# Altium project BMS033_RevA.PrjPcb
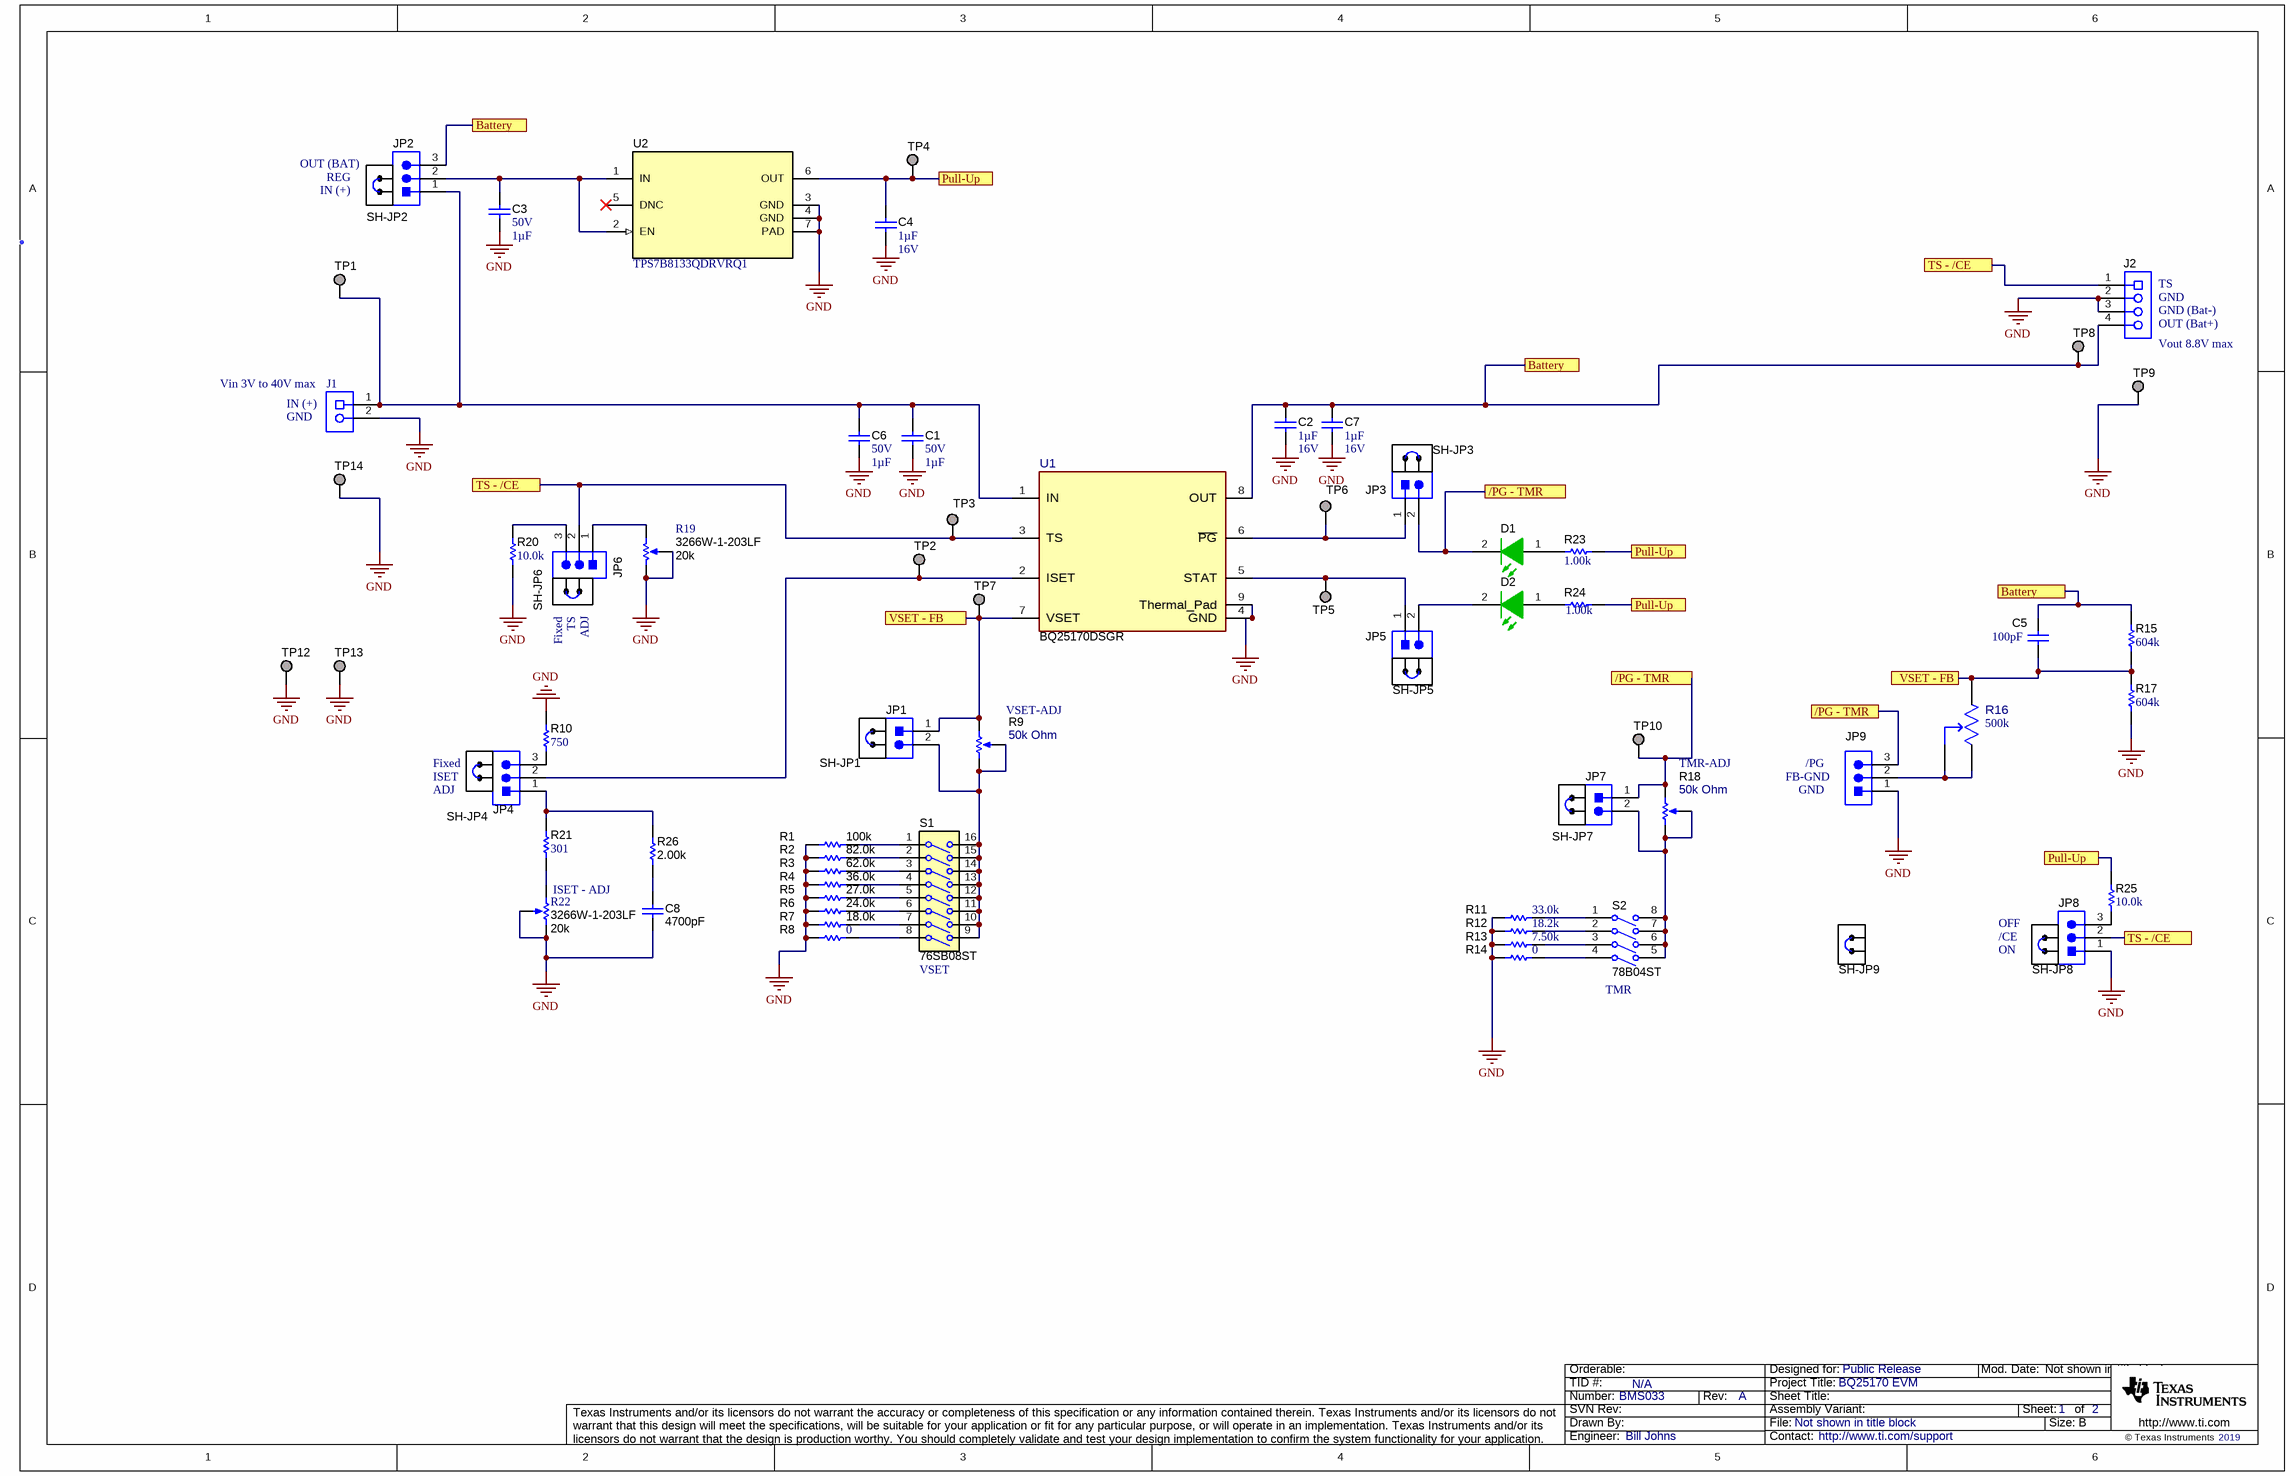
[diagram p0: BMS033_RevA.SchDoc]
CopyrightYear: 2019; PCB_Layout: Krypton Solutions / JMM; PCB_Rev: A; PRJ_Customer: Public Release; PRJ_Engineer: Bill Johns; PRJ_Number: BMS033; PRJ_Title: BQ25170 EVM; SCH_Rev: A; TechSupport: http://www.ti.com/support; TID: N/A
2 sheets, 86 parts. Net scope: flat (ports and power ports of the same name join across sheets).
Board file: BMS033_RevA.PcbDoc
Sheets:
  BMS033_RevA.SchDoc
  BMS033_RevA_Hardware.SchDoc

## Sheet BMS033_RevA.SchDoc
size 431 x 279 mm; Date: Not shown in title block; ApprovedBy: Not shown in title block; CheckedBy: Not shown in title block; Author: Not shown in title block; CompanyName: Not shown in title block; Engineer: Not shown in title block; Organization: Not shown in title block; Address1: Not shown in title block; Address2: Not shown in title block; Address3: Not shown in title block; Address4: Not shown in title block; DocumentNumber: 1; Revision: Use project parameter SCH_Rev; SheetNumber: 1; SheetTotal: 2; PageSetup: Record=PageOptions¦CenterHorizontal=True¦CenterVertical=True¦PrintScale=1.00¦XCorrection=1.00¦YCorrection=1.00¦PrintKind=0¦BorderSize=5000000¦LeftOffset=0¦BottomOffset=0¦Orientation=2¦PaperLength=1000¦PaperWidth=1000¦Scale=100¦PaperSource=15¦PrintQuality=600¦MediaType=1¦DitherType=10¦PaperKind=Letter¦PrintScaleMode=1

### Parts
C1  VDC_V: 50V  ValueDisplayed: 1µF  [0603]  (hidden comment: GRT188R61H105ME13D)
C2  Cap_F: 1µF  VDC_V: 16V  [0603]  (hidden comment: GCM188R71C105KA64D)
C3  VDC_V: 50V  ValueDisplayed: 1µF  [0603]  (hidden comment: GRT188R61H105ME13D)
C4  Cap_F: 1µF  VDC_V: 16V  [0603]  (hidden comment: GCM188R71C105KA64D)
C5  value 100pF  [0402]  (hidden comment: 04025A101FAT2A)
C6  VDC_V: 50V  ValueDisplayed: 1µF  [0603]  (hidden comment: GRT188R61H105ME13D)
C7  Cap_F: 1µF  VDC_V: 16V  [0603]  (hidden comment: GCM188R71C105KA64D)
C8  ValueDisplayed: 4700pF  [0603]  (hidden comment: C0603C104K9PAC7867)
D1  LTST-C193TGKT-5A  [LTST-C193_Green_S]  (value not drawn)
D2  LTST-C193TGKT-5A  [LTST-C193_Green_S]  (value not drawn)
J1  ED555/2DS  [TERM_BLK_ED555-2DS]  (value not drawn)
J2  ED555/4DS  [TERM_BLK_ED555-4DS]  (value not drawn)
JP1  PEC02SAAN  [CONN_PEC02SAAN]  (value not drawn)
JP2  PEC03SAAN  [CONN_PEC03SAAN]  (value not drawn)
JP3  PEC02SAAN  [CONN_PEC02SAAN]  (value not drawn)
JP4  PEC03SAAN  [CONN_PEC03SAAN]  (value not drawn)
JP5  PEC02SAAN  [CONN_PEC02SAAN]  (value not drawn)
JP6  PEC03SAAN  [CONN_PEC03SAAN]  (value not drawn)
JP7  PEC02SAAN  [CONN_PEC02SAAN]  (value not drawn)
JP8  PEC03SAAN  [CONN_PEC03SAAN]  (value not drawn)
JP9  PEC03SAAN  [CONN_PEC03SAAN]  (value not drawn)
R1  ValueDisplayed: 100k  [0603]  (hidden comment: RC0603FR-0775KL)
R2  ValueDisplayed: 82.0k  [0603]  (hidden comment: RC0603FR-0733KL)
R3  ValueDisplayed: 62.0k  [0603]  (hidden comment: RC0603FR-0727K4L)
R4  ValueDisplayed: 36.0k  [0603]  (hidden comment: RC0603FR-0722K1L)
R5  ValueDisplayed: 27.0k  [0603]  (hidden comment: RC0603FR-077K5L)
R6  ValueDisplayed: 24.0k  [0603]  (hidden comment: RC0603FR-075K6L)
R7  ValueDisplayed: 18.0k  [0603]  (hidden comment: RC0603FR-073K32L)
R8  ValueDisplayed: 0  [0603]  (hidden comment: RC0603JR-070RL)
R9  value 50k Ohm  [Bourns_PV37W]  (hidden comment: PV37W503C01B00)
R10  ValueDisplayed: 750  [0603]  (hidden comment: RC0603FR-07750RL)
R11  ValueDisplayed: 33.0k  [0603]  (hidden comment: RC0603FR-0733KL)
R12  ValueDisplayed: 18.2k  [0603]  (hidden comment: RC0603FR-0718K2L)
R13  ValueDisplayed: 7.50k  [0603]  (hidden comment: RC0603FR-077K5L)
R14  ValueDisplayed: 0  [0603]  (hidden comment: RC0603JR-070RL)
R15  ValueDisplayed: 604k  [0805L]  (hidden comment: RT0805BRD07604KL)
R16  PV37W504C01B00  [FP-PV37W504C01B00_PTH_3-MFG]  (value not drawn)
R17  ValueDisplayed: 604k  [0805L]  (hidden comment: RT0805BRD07604KL)
R18  value 50k Ohm  [Bourns_PV37W]  (hidden comment: PV37W503C01B00)
R19  3266W-1-203LF  value 20k  [TRIM_3266W]
R20  ValueDisplayed: 10.0k  [0603]  (hidden comment: CRCW060310K0FKEA)
R21  ValueDisplayed: 301  [0603]  (hidden comment: CRCW0603301RFKEA)
R22  3266W-1-203LF  value 20k  [TRIM_3266W]
R23  ValueDisplayed: 1.00k  [0603]  (hidden comment: RC0603FR-071KL)
R24  ValueDisplayed: 1.00k  [0603]  (hidden comment: RC0603FR-071KL)
R25  ValueDisplayed: 10.0k  [0603]  (hidden comment: CRCW060310K0FKEA)
R26  ValueDisplayed: 2.00k  [0603]  (hidden comment: CRCW06032K00FKEA)
S1  76SB08ST  [SW_76SB08ST]
S2  78B04ST  [SW_78B04ST]
SH-JP1  SNT-100-BK-G  [SNT-100-BK-G]  (value not drawn)
SH-JP2  SNT-100-BK-G  [SNT-100-BK-G]  (value not drawn)
SH-JP3  SNT-100-BK-G  [SNT-100-BK-G]  (value not drawn)
SH-JP4  SNT-100-BK-G  [SNT-100-BK-G]  (value not drawn)
SH-JP5  SNT-100-BK-G  [SNT-100-BK-G]  (value not drawn)
SH-JP6  SNT-100-BK-G  [SNT-100-BK-G]  (value not drawn)
SH-JP7  SNT-100-BK-G  [SNT-100-BK-G]  (value not drawn)
SH-JP8  SNT-100-BK-G  [SNT-100-BK-G]  (value not drawn)
SH-JP9  SNT-100-BK-G  [SNT-100-BK-G]  (value not drawn)
TP1  S1751-46  [Harwin_S1751-46]  (value not drawn)
TP2  S1751-46  [Harwin_S1751-46]  (value not drawn)
TP3  S1751-46  [Harwin_S1751-46]  (value not drawn)
TP4  S1751-46  [Harwin_S1751-46]  (value not drawn)
TP5  S1751-46  [Harwin_S1751-46]  (value not drawn)
TP6  S1751-46  [Harwin_S1751-46]  (value not drawn)
TP7  S1751-46  [Harwin_S1751-46]  (value not drawn)
TP8  S1751-46  [Harwin_S1751-46]  (value not drawn)
TP9  S1751-46  [Harwin_S1751-46]  (value not drawn)
TP10  S1751-46  [Harwin_S1751-46]  (value not drawn)
TP12  S1751-46  [Harwin_S1751-46]  (value not drawn)
TP13  S1751-46  [Harwin_S1751-46]  (value not drawn)
TP14  S1751-46  [Harwin_S1751-46]  (value not drawn)
U1  PartNumber: BQ25170DSGR  [DSG0008A]  (hidden comment: BQ25170DSG)
U2  TPS7B8133QDRVRQ1  [DRV0006A]  (no BOM)

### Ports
/PG - TMR, Battery, Pull-Up, TS - /CE, VSET - FB

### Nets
GND: C1.2 C2.2 C3.2 C4.2 C6.2 C7.2 C8.1 J1.2 J2.2 J2.3 JP8.1 JP9.1 R1.1 R2.1 R3.1 R4.1 R5.1 R6.1 R7.1 R8.1 R10.2 R11.1 R12.1 R13.1 R14.1 R17.1 R19.2(WIPER) R19.3(CW) R20.1 R22.2(WIPER) R22.3(CW) TP9.1 TP12.1 TP13.1 TP14.1 U1.4(GND) U1.9(Thermal_Pad) U2.3(GND) U2.4(GND) U2.7(PAD)
/PG - TMR: D1.2(K) JP3.2 JP7.1 JP9.3 R18.3(CW) TP10.1 ; port /PG - TMR
Battery: C2.1 C5.1 C7.1 J2.4 JP2.3 R15.2 TP8.1 U1.8(OUT) ; port Battery
Pull-Up: C4.1 R23.2 R24.2 R25.2 TP4.1 U2.6(OUT) ; port Pull-Up
TS - /CE: J2.1 JP6.2 JP8.2 TP3.1 U1.3(TS) ; port TS - /CE
VSET - FB: C5.2 JP1.1 R9.3(CW) R15.1 R16.3 R17.2 TP7.1 U1.7(VSET) ; port VSET - FB
NetC1_1: C1.1 C6.1 J1.1 JP2.1 TP1.1 U1.1(IN)
NetC3_1: C3.1 JP2.2 U2.1(IN) U2.2(EN)
NetC8_2: C8.2 R26.2
NetD1_1: D1.1(A) R23.1
NetD2_1: D2.1(A) R24.1
NetD2_2: D2.2(K) JP5.2
NetJP1_2: JP1.2 R9.1(CCW) R9.2(WIPER) S1.9(8A) S1.10(7A) S1.11(6A) S1.12(5A) S1.13(4A) S1.14(3A) S1.15(2A) S1.16(1A)
NetJP3_1: JP3.1 TP6.1 U1.6(~{PG})
NetJP4_1: JP4.1 R21.2 R26.1
NetJP4_2: JP4.2 TP2.1 U1.2(ISET)
NetJP4_3: JP4.3 R10.1
NetJP5_1: JP5.1 TP5.1 U1.5(STAT)
NetJP6_1: JP6.1 R19.1(CCW)
NetJP6_3: JP6.3 R20.2
NetJP7_2: JP7.2 R18.1(CCW) R18.2(WIPER) S2.5(B4) S2.6(B3) S2.7(B2) S2.8(B1)
NetJP8_3: JP8.3 R25.1
NetJP9_2: JP9.2 R16.1 R16.2
NetR1_2: R1.2 S1.1
NetR2_2: R2.2 S1.2
NetR3_2: R3.2 S1.3
NetR4_2: R4.2 S1.4
NetR5_2: R5.2 S1.5
NetR6_2: R6.2 S1.6
NetR7_2: R7.2 S1.7
NetR8_2: R8.2 S1.8
NetR11_2: R11.2 S2.1(A1)
NetR12_2: R12.2 S2.2(A2)
NetR13_2: R13.2 S2.3(A3)
NetR14_2: R14.2 S2.4(A4)
NetR21_1: R21.1 R22.1(CCW)

Not connected (* = marked no-connect by the designer): U2 5(DNC)*

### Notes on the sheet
- (near SH-JP2) OUT (BAT)
- (near SH-JP2) IN (+)
- (near SH-JP2) REG
- (near J2) GND
- (near J2) TS
- (near J2) GND (Bat-)
- (near J2) OUT (Bat+)
- Vout 8.8V max
- (near J1) Vin 3V to 40V max
- (near J1) IN (+)
- GND
- (near SH-JP6) TS
- (near SH-JP6) Fixed
- (near SH-JP6) ADJ
- (near R9) VSET-ADJ
- (near SH-JP4) Fixed
- (near SH-JP4) ISET
- (near SH-JP4) ADJ
- TMR-ADJ
- (near JP9) FB-GND
- (near JP9) /PG
- (near R22) ISET - ADJ
- (near SH-JP8) OFF
- (near SH-JP8) /CE
- (near SH-JP8) ON
- (near S1) VSET
- (near S2) TMR

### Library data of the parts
C1 C3 C6 = CMP-0081784-1: CAP, CERM, 1 µF, 50 V,+/- 20%, X5R, AEC-Q200 Grade 3, 0603; Manufacturer: MuRata; TaMin_C: -55°C; Polarized: N; SizeAreaWB_mm2: 4.68; U/M: EA; Value: 1uF; TaMax_C: 85°C; SizeZ_mm: 1; SizeX_mm: 1.6; SizeY_mm: 0.8; SizeArea_mm2: 1.28; CompType: Capacitor; AEC Qualified: Y; AEC Grade: 3; AEC Category: Q200
C2 C4 C7 = CMP-0007136-5: CAP, CERM, 1 uF, 16 V, +/- 10%, X7R, AEC-Q200 Grade 1, 0603; Manufacturer: MuRata; TaMin_C: -55°C; Polarized: N; SizeAreaWB_mm2: 4.68; Value1: Unknown; U/M: EA; Value: 1uF; TaMax_C: 125°C; SizeZ_mm: 1; SizeX_mm: 1.6; SizeY_mm: 0.8; SizeArea_mm2: 1.28; CompType: Capacitor; AEC Qualified: Y; AEC Category: Q200
C5 = CMP-0006196-2: CAP, CERM, 100 pF, 50 V, +/- 1%, C0G/NP0, 0402; Manufacturer: AVX; TaMin_C: -55°C; Polarized: N; SizeAreaWB_mm2: 3; Value1: Unknown; U/M: EA; TaMax_C: 125°C; SizeZ_mm: 0.6; SizeX_mm: 1; SizeY_mm: 0.5; Value2: 50V; CompType: Capacitor; AEC Category: Q200; ValueDisplayed: DNI
C8 = CMP-0007354-5: CAP, CERM, 4700 pF, 50 V, +/- 10%, X5R, 0603; Manufacturer: MuRata; PartNumber: GRM188R61H472KA01D; TaMin_C: -55°C; Polarized: N; SizeAreaWB_mm2: 4.68; Value1: Unknown; U/M: EA; Value: 4700pF; TaMax_C: 85°C; SizeZ_mm: 1; SizeX_mm: 1.6; SizeY_mm: 0.8; Value2: 50V; SizeArea_mm2: 1.28; Cap_F: 4.7nF; AEC Category: Q200
D1 D2 = CMP-0080580-2: LED, Green, SMD; Manufacturer: Lite-On; SizeZ_mm: 0.45; SizeX_mm: 1.6; Angle: 130; SizeArea_mm2: 1.28; Power_TotalModule: 76mW; Vf_V: 2.8V; Io_A: 5mA; SizeAreaWB_mm2: 4.68; Type: InGaN; Ir_A: 10µA; Value1: 0.076W; Tjmax_C: 80°C; SizeY_mm: 0.8; Vr_V: 5V
J1 = CMP-0074913-1: Terminal Block, 3.5mm Pitch, 2x1, TH; Manufacturer: On-Shore Technology; Cert_VDE: Y; CNHeader: False; Current_A: 6A; Green_Lifecycle: Active; Shrouded: N; Gender: Female; Green_REACh: Passed; Voltage_V: 150V; Row_Count: 1; Pitch_mm: 3.5; ContactFinish: Brass; CT: True
J2 = CMP-0074917-1: Terminal Block, 3.5mm Pitch, 4x1, TH; Manufacturer: On-Shore Technology; Cert_VDE: Y; CNHeader: False; Current_A: 6A; Green_Lifecycle: Not Set; Shrouded: N; Gender: Female; Green_REACh: Incomplete; Voltage_V: 150V; Row_Count: 1; Pitch_mm: 3.5; ContactFinish: Brass; CT: True
JP1 JP3 JP5 JP7 = CMP-0002337-1: Header, 100mil, 2x1, Tin, TH; Manufacturer: Sullins Connector Solutions; CNHeader: TRUE; Current_A: 3A; Green_Lifecycle: Not Set; Shrouded: N; Gender: Male; Green_REACh: Incomplete; Voltage_V: 1.8kV; Row_Count: 1; Pitch_mm: 2.54; CT: FALSE; Cert_UL: Y
JP2 JP4 JP6 JP8 JP9 = CMP-0002338-1: Header, 100mil, 3x1, Tin, TH; Manufacturer: Sullins Connector Solutions; CNHeader: TRUE; Current_A: 3A; Green_Lifecycle: Not Set; Shrouded: N; Gender: Male; Green_REACh: Incomplete; Voltage_V: 1.8kV; Row_Count: 1; Pitch_mm: 2.54; CT: FALSE; Cert_UL: Y
R1 = CMP-0022735-5: RES, 100 k, 1%, 0.1 W, 0603; Manufacturer: Yageo; PartNumber: RC0603FR-07100KL; Power_W: 100mW; TempCo: 100 ppm/C; Value: 100k; EIA_Code: E96; SizeX_mm: 1.6; SizeY_mm: 0.8; SizeZ_mm: 1; Value2: 0.1W; SizeArea_mm2: 1.28; AEC Qualified: N; VDC_V: 75V; AEC Category: Q200; SizeAreaWB_mm2: 4.68
R2 = CMP-0023292-5: RES, 82.0 k, 1%, 0.1 W, 0603; Manufacturer: Yageo; PartNumber: RC0603FR-0782KL; Power_W: 100mW; TempCo: 100 ppm/C; Value_Code: 82k0; Value: 82.0k; Res_ohm: 82k; SizeX_mm: 1.6; SizeY_mm: 0.8; SizeZ_mm: 1; Value2: 0.1W; SizeArea_mm2: 1.28; AEC Qualified: N; VDC_V: 75V; AEC Category: Q200; SizeAreaWB_mm2: 4.68
R3 = CMP-0023220-5: RES, 62.0 k, 1%, 0.1 W, 0603; Manufacturer: Yageo; PartNumber: RC0603FR-0762KL; Power_W: 100mW; TempCo: 100 ppm/C; Value_Code: 62k0; Value: 62.0k; Res_ohm: 62k; SizeX_mm: 1.6; SizeY_mm: 0.8; SizeZ_mm: 1; Value2: 0.1W; SizeArea_mm2: 1.28; AEC Qualified: N; VDC_V: 75V; AEC Category: Q200; SizeAreaWB_mm2: 4.68
R4 = CMP-0023057-5: RES, 36.0 k, 1%, 0.1 W, 0603; Manufacturer: Yageo; PartNumber: RC0603FR-0736KL; Power_W: 100mW; TempCo: 100 ppm/C; Value_Code: 36k0; Value: 36.0k; Res_ohm: 36k; SizeX_mm: 1.6; SizeY_mm: 0.8; SizeZ_mm: 1; Value2: 0.1W; SizeArea_mm2: 1.28; AEC Qualified: N; VDC_V: 75V; AEC Category: Q200; SizeAreaWB_mm2: 4.68
R5 = CMP-0022966-5: RES, 27.0 k, 1%, 0.1 W, 0603; Manufacturer: Yageo; PartNumber: RC0603FR-0727KL; Power_W: 100mW; TempCo: 100 ppm/C; Value_Code: 27k0; Value: 27.0k; Res_ohm: 27k; SizeX_mm: 1.6; SizeY_mm: 0.8; SizeZ_mm: 1; Value2: 0.1W; SizeArea_mm2: 1.28; AEC Qualified: N; VDC_V: 75V; AEC Category: Q200; SizeAreaWB_mm2: 4.68
R6 = CMP-0022945-5: RES, 24.0 k, 1%, 0.1 W, 0603; Manufacturer: Yageo; PartNumber: RC0603FR-0724KL; Power_W: 100mW; TempCo: 100 ppm/C; Value_Code: 24k0; Value: 24.0k; Res_ohm: 24k; SizeX_mm: 1.6; SizeY_mm: 0.8; SizeZ_mm: 1; Value2: 0.1W; SizeArea_mm2: 1.28; AEC Qualified: N; VDC_V: 75V; AEC Category: Q200; SizeAreaWB_mm2: 4.68
R7 = CMP-0022852-5: RES, 18.0 k, 1%, 0.1 W, 0603; Manufacturer: Yageo; PartNumber: RC0603FR-0718KL; Power_W: 100mW; TempCo: 100 ppm/C; Value_Code: 18k0; Value: 18.0k; Res_ohm: 18k; SizeX_mm: 1.6; SizeY_mm: 0.8; SizeZ_mm: 1; Value2: 0.1W; SizeArea_mm2: 1.28; AEC Qualified: N; VDC_V: 75V; AEC Category: Q200; SizeAreaWB_mm2: 4.68
R8 R14 = CMP-0025885-5: RES, 0, 5%, 0.1 W, 0603; Manufacturer: Yageo; Power_W: 100mW; TempCo: 200 ppm/C; Value_Code: 0000; Value: 0; EIA_Code: E24; SizeX_mm: 1.6; SizeZ_mm: 1; Value2: 0.1W; SizeArea_mm2: 1.28; CompType: Resistor; AEC Qualified: N; VDC_V: 75V; AEC Category: Q200; SizeY_mm: 0.8; SizeAreaWB_mm2: 4.68
R9 R18 = CMP-0001794-2: Trimmer Potentiometer, Lead Sealed Type Multiturn PV37 Series, TH; Manufacturer: Bourns; SizeX_mm: 6.71; SizeY_mm: 4.5; SizeZ_mm: 8.39; SizeArea_mm2: 30.195; SizeAreaWB_mm2: 56.615
R10 = CMP-0023266-5: RES, 750, 1%, 0.1 W, 0603; Manufacturer: Yageo; Power_W: 100mW; TempCo: 100 ppm/C; Value_Code: 750R; Value: 750; EIA_Code: E96; SizeX_mm: 1.6; SizeY_mm: 0.8; SizeZ_mm: 1; Value2: 0.1W; SizeArea_mm2: 1.28; AEC Qualified: N; VDC_V: 75V; AEC Category: Q200; SizeAreaWB_mm2: 4.68
R11 = CMP-0023037-5: RES, 33.0 k, 1%, 0.1 W, 0603; Manufacturer: Yageo; Power_W: 100mW; TempCo: 100 ppm/C; Value_Code: 33k0; Value: 33.0k; Res_ohm: 33k; SizeX_mm: 1.6; SizeY_mm: 0.8; SizeZ_mm: 1; Value2: 0.1W; SizeArea_mm2: 1.28; AEC Qualified: N; VDC_V: 75V; AEC Category: Q200; SizeAreaWB_mm2: 4.68
R12 = CMP-0022850-5: RES, 18.2 k, 1%, 0.1 W, 0603; Manufacturer: Yageo; Power_W: 100mW; TempCo: 100 ppm/C; Value_Code: 18k2; Value: 18.2k; EIA_Code: E96; SizeX_mm: 1.6; SizeY_mm: 0.8; SizeZ_mm: 1; Value2: 0.1W; SizeArea_mm2: 1.28; CompType: Resistor; AEC Qualified: N; VDC_V: 75V; AEC Category: Q200; SizeAreaWB_mm2: 4.68
R13 = CMP-0023279-5: RES, 7.50 k, 1%, 0.1 W, 0603; Manufacturer: Yageo; Power_W: 100mW; TempCo: 100 ppm/C; Value_Code: 7k50; Value: 7.50k; EIA_Code: E96; Res_ohm: 7.5k; SizeX_mm: 1.6; SizeY_mm: 0.8; SizeZ_mm: 1; Value2: 0.1W; SizeArea_mm2: 1.28; CompType: Resistor; AEC Qualified: N; VDC_V: 75V; AEC Category: Q200; SizeAreaWB_mm2: 4.68
R15 R17 = CMP-0020221-2: RES, 604 k, 0.1%, 0.125 W, 0805; Manufacturer: Yageo America; Power_W: 125mW; TempCo: 25 ppm/C; U/M: EA; Value: 604k; EIA_Code: E192; SizeX_mm: 2; SizeY_mm: 1.25; SizeZ_mm: 1.45; Value2: 0.125W; SizeArea_mm2: 2.5; CompType: Resistor; VDC_V: 150V; AEC Category: Q200
R16 = CMP-0088264-1: 500 kOhms 0.25W, 1/4W PC Pins Through Hole Trimmer Potentiometer Cermet 12 Turn Top Adjustment; Manufacturer: Bourns; SizeZ_mm: 9.02mm; Symbol Name: SYM-PV37W504C01B00
R19 R22 = CMP-0002068-2: Trimmer, 20k ohm, 0.25W, TH; Manufacturer: Bourns
R20 R25 = CMP-0021998-4: RES, 10.0 k, 1%, 0.1 W, AEC-Q200 Grade 0, 0603; Manufacturer: Vishay-Dale; Power_W: 100mW; TempCo: 100 ppm/C; Value_Code: 10k0; Value: 10.0k; EIA_Code: E96; Res_ohm: 10k; SizeX_mm: 1.6; SizeY_mm: 0.8; SizeZ_mm: 1; Value2: 0.1W; SizeArea_mm2: 1.28; AEC Qualified: Y; VDC_V: 75V; AEC Category: Q200; AEC Grade: 0
R21 = CMP-0022321-5: RES, 301, 1%, 0.1 W, AEC-Q200 Grade 0, 0603; Manufacturer: Vishay-Dale; Power_W: 100mW; TempCo: 100 ppm/C; Value_Code: 301R; Value: 301; EIA_Code: E96; SizeX_mm: 1.6; SizeY_mm: 0.8; SizeZ_mm: 1; Value2: 0.1W; SizeArea_mm2: 1.28; AEC Qualified: Y; VDC_V: 75V; AEC Category: Q200; AEC Grade: 0
R23 R24 = CMP-0022895-5: RES, 1.00 k, 1%, 0.1 W, 0603; Manufacturer: Yageo; Power_W: 100mW; TempCo: 100 ppm/C; Value_Code: 1k00; Value: 1.00k; EIA_Code: E96; Res_ohm: 1k; SizeX_mm: 1.6; SizeY_mm: 0.8; SizeZ_mm: 1; Value2: 0.1W; SizeArea_mm2: 1.28; AEC Qualified: N; VDC_V: 75V; AEC Category: Q200; SizeAreaWB_mm2: 4.68
R26 = CMP-0022268-4: RES, 2.00 k, 1%, 0.1 W, AEC-Q200 Grade 0, 0603; Manufacturer: Vishay-Dale; Power_W: 100mW; TempCo: 100 ppm/C; Value_Code: 2k00; Value: 2.00k; EIA_Code: E96; Res_ohm: 2k; SizeX_mm: 1.6; SizeY_mm: 0.8; SizeZ_mm: 1; Value2: 0.1W; SizeArea_mm2: 1.28; CompType: Resistor; AEC Qualified: Y; VDC_V: 75V; AEC Category: Q200; AEC Grade: 0
S1 = CMP-0002117-2: Switch, SPST 8Pos, Rocker, TH; Manufacturer: Grayhill; CurrentRating_mA: 150A; PositionCount: 8; VDC_V: 30V; SwitchFunction: Off-On
S2 = CMP-0002130-2: DIP Switch, SPST 4Pos, Slide, TH; Manufacturer: Grayhill; CurrentRating_mA: 150A; PositionCount: 4; VDC_V: 30V; SwitchFunction: Off-On
SH-JP1-SH-JP9 = CMP-0003623-3: Shunt, 100mil, Gold plated, Black; Alternate PartNumber: 969102-0000-DA; Manufacturer: Samtec; Alternate Manufacturer: 3M; Value: 1x2
TP1-TP10 TP12-TP14 = CMP-0075188-1: Test Lead clips and hooks, SMT; Manufacturer: Harwin; CNHeader: False; Current_A: 2A; CompType: Test Point; ContactFinish: Tin; CT: True
U1 = CMP-0096741-1: 800-mA Linear Battery Charger for 1-Cell Li-Ion, and LiFePO4; Manufacturer: Texas Instruments; AEC Qualified: No; Nominal Supply Current: 0.45mA; Max Supply Voltage: 6.6V; Number Of Cells: 1; Standoff Height: 0mm; SizeZ_mm: 0.8mm; Output Voltage: 4.4V; TJmax_C: +125°C; Min Supply Voltage: 3V
U2 = CMP-0860463-1: Automotive 150-mA high-voltage ultra-low-IQ low-dropout (LDO) linear regulator, DRV0006A (WSON-6); Alternate Manufacturer: Texas Instruments; AEC Qualified: Y; SizeY_mm: 2; SizeZ_mm: 0.8; AEC Category: Q200; CompType: IC; SizeArea_mm2: 4; SizeAreaWB_mm2: 9

## Sheet BMS033_RevA_Hardware.SchDoc
size 431 x 279 mm; Date: Not shown in title block; ApprovedBy: Not shown in title block; CheckedBy: Not shown in title block; Author: Not shown in title block; CompanyName: Not shown in title block; Engineer: Not shown in title block; Organization: Not shown in title block; Address1: Not shown in title block; Address2: Not shown in title block; Address3: Not shown in title block; Address4: Not shown in title block; DocumentNumber: 1; Revision: Use project parameter SCH_Rev; SheetNumber: 2; SheetTotal: 2; PageSetup: Record=PageOptions¦CenterHorizontal=True¦CenterVertical=True¦PrintScale=1.00¦XCorrection=1.00¦YCorrection=1.00¦PrintKind=0¦BorderSize=5000000¦LeftOffset=0¦BottomOffset=0¦Orientation=2¦PaperLength=1000¦PaperWidth=1000¦Scale=100¦PaperSource=15¦PrintQuality=600¦MediaType=1¦DitherType=10¦PaperKind=Letter¦PrintScaleMode=1
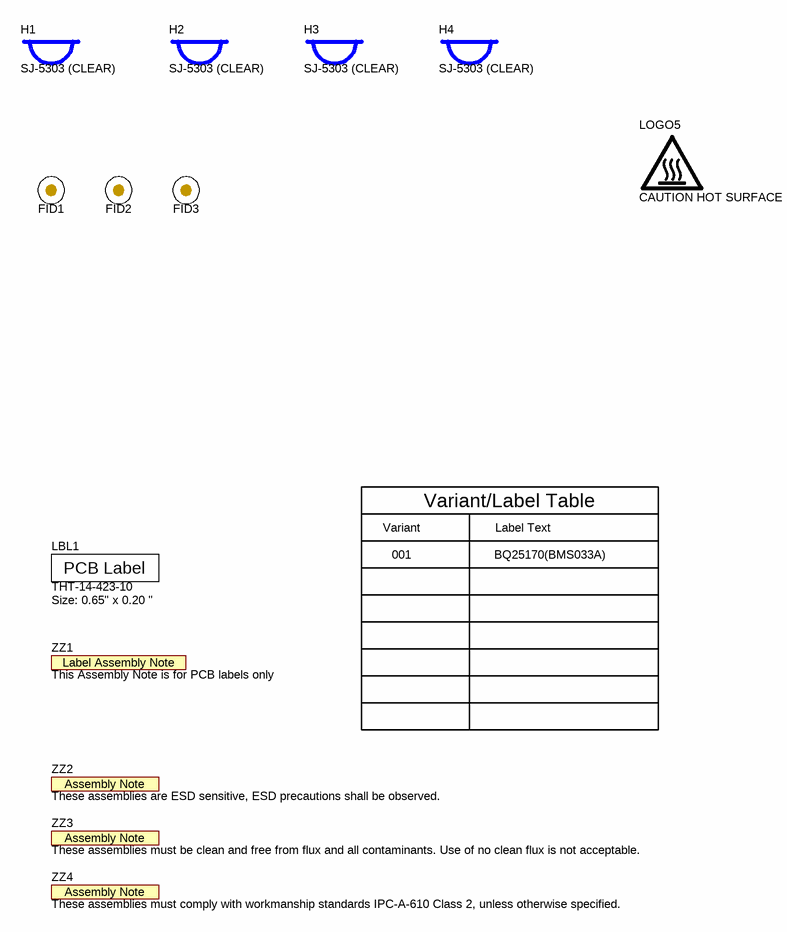
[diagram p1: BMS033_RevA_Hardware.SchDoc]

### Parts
FID1  Fiducial  [Fiducial10-20]  (value not drawn)
FID2  Fiducial  [Fiducial10-20]  (value not drawn)
FID3  Fiducial  [Fiducial10-20]  (value not drawn)
H1  SJ-5303 (CLEAR)  [Bumpon_SJ5003Transparent]
H2  SJ-5303 (CLEAR)  [Bumpon_SJ5003Transparent]
H3  SJ-5303 (CLEAR)  [Bumpon_SJ5003Transparent]
H4  SJ-5303 (CLEAR)  [Bumpon_SJ5003Transparent]
LBL1  THT-14-423-10  Note: Size: 0.65" x 0.20 "  [Label_650x200]
LOGO5  CAUTION HOT SURFACE  [IEC_HotSurface_Small]  (no BOM)
ZZ1  This Assembly Note is for PCB labels only  [AssemblyNoteLabel]  (no BOM)
ZZ2  These assemblies are ESD sensitive, ESD precautions shall be observed.  [AssemblyNote]  (no BOM)
ZZ3  These assemblies must be clean and free from flux and all contaminants. Use of no clean flux is not acceptable.  [AssemblyNote]  (no BOM)
ZZ4  These assemblies must comply with workmanship standards IPC-A-610 Class 2, unless otherwise specified.  [AssemblyNote]  (no BOM)

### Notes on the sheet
- Variant
- Variant/Label Table
- Label Text
- 001
- BQ25170(BMS033A)

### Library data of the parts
FID1-FID3 = CMP-0077181-1: Fiducial mark.  There is nothing to buy or mount.
H1-H4 = CMP-0003620-1: Bumpon, Hemisphere, 0.44 X 0.20, Clear; Manufacturer: 3M
LBL1 = CMP-0003625-1: Thermal Transfer Printable Labels, 0.650" W x 0.200" H - 10,000 per roll; Manufacturer: Brady; CompType: Label
LOGO5 = CMP-0074837-1: IEC 61010-1 Hot Surface Warning; Library Reference: IEC_HotSurface; SymbolCreator: a0412235
ZZ1 = CMP-0003616-3
ZZ2 = CMP-0077236-1
ZZ3 = CMP-0077237-1
ZZ4 = CMP-0077238-1

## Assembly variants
001: not fitted C5 C6 C7 C8 FID1 FID2 FID3 JP7 JP8 JP9 R11 R12 R13 R14 R15 R16 R17 R18 R25 R26 R27 S2 SH-JP8 SH-JP9; alternate parts R21 -> CMP-0082532-1, R22 -> CMP-0001795-1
